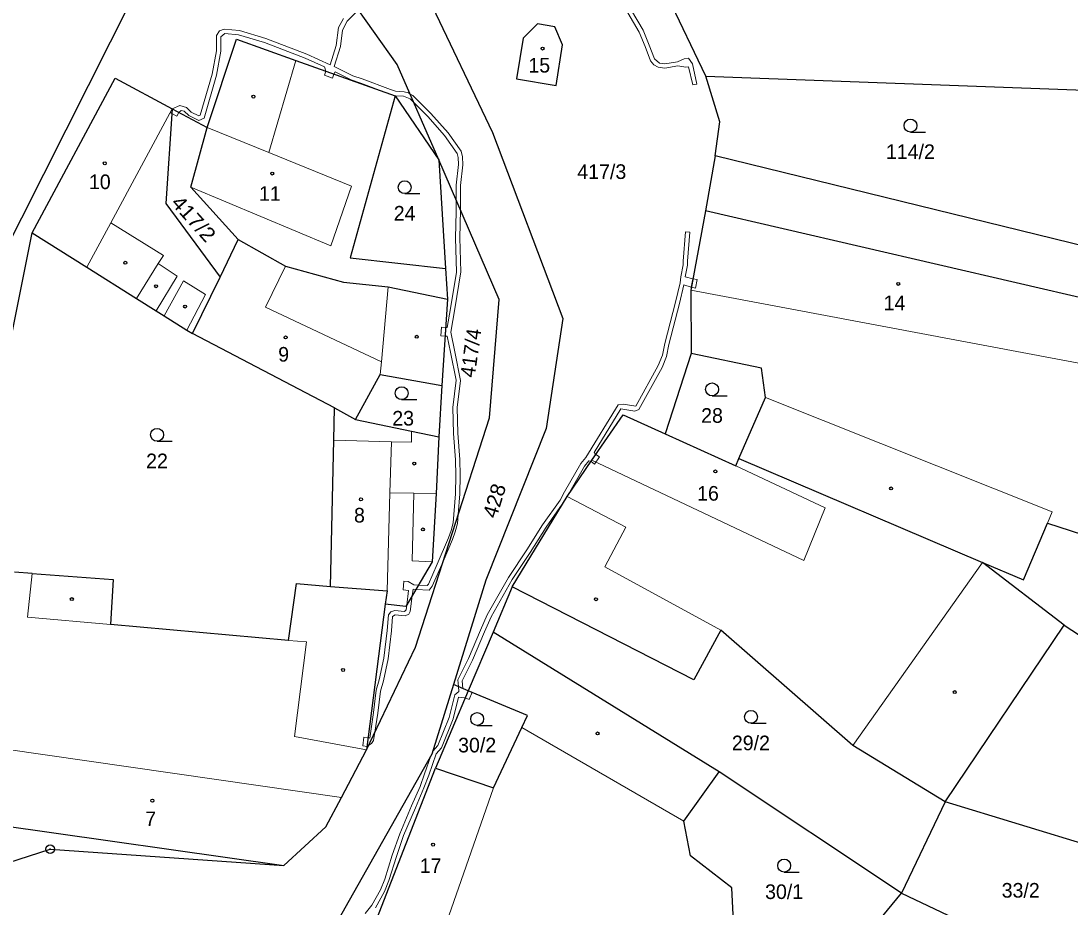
# Model space of a CAD drawing. Extents: x -791548 to -789311, y -1142631 to -1140855.
# Drawn here: x -790327.9 to -790206, y -1142218.6 to -1142115.7 of the extents above; entities that cross this region are included whole.
import ezdxf
from ezdxf.enums import TextEntityAlignment as Align

# ---------------------------------------------------------------- set-up
doc = ezdxf.new("R2010")
doc.units = 0
doc.header["$LTSCALE"] = 0.68
for name, color, linetype, lineweight in [('1', 7, 'Continuous', 25), ('13', 7, 'Continuous', 13), ('3', 7, 'Continuous', 25), ('4', 7, 'Continuous', 13), ('5', 7, 'Continuous', 25), ('8', 7, 'Continuous', 25)]:
    doc.layers.add(name, color=color, linetype=linetype, lineweight=lineweight)
doc.layers.add('2', color=7, linetype='Continuous')

msp = doc.modelspace()

# ---------------------------------------------------------------- linework, layer by layer
at = {"layer": '1'}
for p, q in [((-790284.19, -1142120.71), (-790294.25, -1142106.51)), ((-790248.33, -1142122.09), (-790253.96, -1142110.28)), ((-790330.46, -1142143.68), (-790314.29, -1142111.65)), ((-790280.51, -1142113.07), (-790273.1, -1142128.64)), ((-790267.88, -1142115.98), (-790269.54, -1142117.64)), ((-790265.88, -1142116.33), (-790267.88, -1142115.98)), ((-790264.98, -1142118.43), (-790265.88, -1142116.33)), ((-790306.29, -1142128.03), (-790302.86, -1142117.79)), ((-790302.86, -1142117.79), (-790295.98, -1142120.26)), ((-790265.7, -1142123.15), (-790264.98, -1142118.43)), ((-790295.98, -1142120.26), (-790284.42, -1142124.37)), ((-790279.36, -1142131.81), (-790284.19, -1142120.71)), ((-790326.62, -1142140.29), (-790316.96, -1142122.32)), ((-790316.96, -1142122.32), (-790310.35, -1142125.86)), ((-790248.33, -1142122.09), (-790202.6, -1142123.76)), ((-790246.69, -1142127.37), (-790248.33, -1142122.09)), ((-790284.42, -1142124.37), (-790289.66, -1142143.18)), ((-790284.42, -1142124.37), (-790279.36, -1142131.81)), ((-790310.35, -1142125.86), (-790311.1, -1142136.86)), ((-790310.35, -1142125.86), (-790306.29, -1142128.03)), ((-790247.24, -1142131.35), (-790246.69, -1142127.37)), ((-790308.18, -1142134.98), (-790306.29, -1142128.03)), ((-790273.1, -1142128.64), (-790264.92, -1142150.23)), ((-790272.32, -1142148.02), (-790279.36, -1142131.81)), ((-790279.36, -1142131.81), (-790278.58, -1142144.41)), ((-790247.24, -1142131.35), (-790248.37, -1142137.71)), ((-790203.93, -1142141.96), (-790247.24, -1142131.35)), ((-790302.66, -1142141.04), (-790308.18, -1142134.98)), ((-790311.1, -1142136.86), (-790304.75, -1142145.45)), ((-790248.37, -1142137.71), (-790250.07, -1142146.94)), ((-790202.22, -1142148.44), (-790248.37, -1142137.71)), ((-790329.14, -1142152.86), (-790326.62, -1142140.29)), ((-790326.62, -1142140.29), (-790320.27, -1142144.28)), ((-790304.75, -1142145.45), (-790302.66, -1142141.04)), ((-790302.66, -1142141.04), (-790297.19, -1142144.14)), ((-790289.66, -1142143.18), (-790278.58, -1142144.41)), ((-790320.27, -1142144.28), (-790314.51, -1142147.9)), ((-790297.19, -1142144.14), (-790290.44, -1142146.01)), ((-790278.58, -1142144.41), (-790278.35, -1142148.01)), ((-790307.99, -1142151.97), (-790304.75, -1142145.45)), ((-790290.44, -1142146.01), (-790285.25, -1142146.56)), ((-790285.25, -1142146.56), (-790278.35, -1142148.01)), ((-790250.07, -1142146.94), (-790250.03, -1142154.31)), ((-790314.51, -1142147.9), (-790312.21, -1142149.34)), ((-790278.35, -1142148.01), (-790278.99, -1142158.03)), ((-790273.47, -1142161.79), (-790272.32, -1142148.02)), ((-790312.21, -1142149.34), (-790311.29, -1142149.92)), ((-790311.29, -1142149.92), (-790308.65, -1142151.58)), ((-790264.92, -1142150.23), (-790266.89, -1142163.02)), ((-790308.65, -1142151.58), (-790307.99, -1142151.97)), ((-790291.47, -1142160.63), (-790307.99, -1142151.97)), ((-790250.03, -1142154.31), (-790253.04, -1142163.65)), ((-790241.85, -1142156.02), (-790250.03, -1142154.31)), ((-790241.38, -1142159.41), (-790241.85, -1142156.02)), ((-790289.04, -1142161.96), (-790286.17, -1142156.76)), ((-790286.17, -1142156.76), (-790278.99, -1142158.03)), ((-790278.99, -1142158.03), (-790279.37, -1142163.99)), ((-790244.48, -1142166.53), (-790241.38, -1142159.41)), ((-790291.55, -1142164.4), (-790291.47, -1142160.63)), ((-790291.47, -1142160.63), (-790289.04, -1142161.96)), ((-790261.55, -1142166.71), (-790257.93, -1142161.43)), ((-790257.93, -1142161.43), (-790253.04, -1142163.65)), ((-790289.04, -1142161.96), (-790282.51, -1142163.33)), ((-790282.08, -1142188.44), (-790273.47, -1142161.79)), ((-790282.51, -1142163.33), (-790279.37, -1142163.99)), ((-790279.37, -1142163.99), (-790279.68, -1142170.57)), ((-790266.89, -1142163.02), (-790273.87, -1142180.67)), ((-790253.04, -1142163.65), (-790244.85, -1142167.37)), ((-790291.96, -1142181.38), (-790291.55, -1142164.4)), ((-790264.45, -1142170.93), (-790261.55, -1142166.71)), ((-790244.85, -1142167.37), (-790244.48, -1142166.53)), ((-790244.48, -1142166.53), (-790216.16, -1142178.61)), ((-790279.68, -1142170.57), (-790280.12, -1142178.53)), ((-790270.84, -1142181.44), (-790264.45, -1142170.93)), ((-790211.41, -1142180.63), (-790208.6, -1142174.01)), ((-790208.6, -1142174.01), (-790196.56, -1142177.95)), ((-790280.12, -1142178.53), (-790283.17, -1142183.7)), ((-790206.67, -1142185.87), (-790216.16, -1142178.61)), ((-790216.16, -1142178.61), (-790211.41, -1142180.63)), ((-790326.63, -1142179.87), (-790328.69, -1142179.71)), ((-790326.63, -1142179.87), (-790317.2, -1142180.56)), ((-790317.2, -1142180.56), (-790317.53, -1142185.8)), ((-790296.82, -1142187.65), (-790295.91, -1142181.06)), ((-790295.91, -1142181.06), (-790291.96, -1142181.38)), ((-790273.87, -1142180.67), (-790277.65, -1142192.79)), ((-790291.96, -1142181.38), (-790285.36, -1142181.91)), ((-790285.36, -1142181.91), (-790285.6, -1142183.44)), ((-790270.84, -1142181.44), (-790273.05, -1142186.68)), ((-790249.71, -1142192.23), (-790270.84, -1142181.44)), ((-790285.6, -1142183.44), (-790287.75, -1142200.37)), ((-790283.17, -1142183.7), (-790285.6, -1142183.44)), ((-790296.82, -1142187.65), (-790317.53, -1142185.8)), ((-790220.5, -1142206.42), (-790206.67, -1142185.87)), ((-790206.67, -1142185.87), (-790191, -1142196.24)), ((-790273.05, -1142186.68), (-790275.93, -1142193.5)), ((-790246.77, -1142202.93), (-790273.05, -1142186.68)), ((-790246.58, -1142186.47), (-790249.71, -1142192.23)), ((-790231.23, -1142199.87), (-790246.58, -1142186.47)), ((-790287.75, -1142200.37), (-790282.08, -1142188.44)), ((-790277.65, -1142192.79), (-790280.17, -1142200.89)), ((-790275.93, -1142193.5), (-790277.65, -1142192.79)), ((-790275.93, -1142193.5), (-790279.72, -1142202.49)), ((-790269.06, -1142196.4), (-790275.93, -1142193.5)), ((-790269.71, -1142197.79), (-790269.06, -1142196.4)), ((-790273, -1142204.78), (-790269.71, -1142197.79)), ((-790290.68, -1142205.92), (-790287.75, -1142200.37)), ((-790220.5, -1142206.42), (-790231.23, -1142199.87)), ((-790280.17, -1142200.89), (-790291.64, -1142221.17)), ((-790286.57, -1142220), (-790279.72, -1142202.49)), ((-790279.72, -1142202.49), (-790273, -1142204.78)), ((-790250.88, -1142208.65), (-790246.77, -1142202.93)), ((-790225.57, -1142217.02), (-790246.77, -1142202.93)), ((-790292.47, -1142209.32), (-790290.68, -1142205.92)), ((-790220.5, -1142206.42), (-790225.57, -1142217.02)), ((-790197.2, -1142213.53), (-790220.5, -1142206.42)), ((-790331.39, -1142209), (-790297.38, -1142213.8)), ((-790250.11, -1142212.7), (-790250.88, -1142208.65)), ((-790297.38, -1142213.8), (-790292.47, -1142209.32)), ((-790336.95, -1142215.9), (-790324.53, -1142211.91)), ((-790324.53, -1142211.91), (-790297.38, -1142213.8)), ((-790245.28, -1142216.42), (-790250.11, -1142212.7)), ((-790245.13, -1142219.55), (-790245.28, -1142216.42)), ((-790234.29, -1142227.54), (-790225.57, -1142217.02)), ((-790225.57, -1142217.02), (-790202.5, -1142227.96))]:
    msp.add_line(p, q, dxfattribs=at)
msp.add_lwpolyline([(-790269.54, -1142117.64), (-790270.34, -1142122.38), (-790265.7, -1142123.15)], dxfattribs=at)
at = {"layer": '13'}
for points in [[(-790290.42, -1142115.39), (-790291, -1142116.4), (-790291.27, -1142118.52), (-790291.98, -1142120.76), (-790294.7, -1142119.52), (-790299.46, -1142117.7), (-790302.54, -1142116.77), (-790304.29, -1142116.62), (-790304.84, -1142116.79), (-790305.19, -1142117.35), (-790305.2, -1142119.12), (-790305.68, -1142121.85), (-790307.08, -1142126.61), (-790307.23, -1142126.68), (-790308.12, -1142126.24), (-790308.7, -1142125.72), (-790309.47, -1142125.5), (-790310.35, -1142125.86), (-790310.39, -1142126.41), (-790309.81, -1142126.72), (-790309.57, -1142126.28), (-790309.29, -1142126.07), (-790308.94, -1142126.16), (-790308.4, -1142126.66), (-790307.23, -1142127.24), (-790306.62, -1142126.94), (-790305.2, -1142121.97), (-790304.7, -1142119.16), (-790304.69, -1142117.49), (-790304.23, -1142117.12), (-790302.64, -1142117.27), (-790299.62, -1142118.18), (-790294.9, -1142119.98), (-790292.65, -1142121), (-790292.49, -1142121.5), (-790291.55, -1142121.83), (-790291.4, -1142121.57), (-790289.54, -1142122.49), (-790288.41, -1142122.88), (-790285.14, -1142124.11), (-790284.42, -1142124.37), (-790283.46, -1142124.38), (-790282.7, -1142124.71), (-790282.26, -1142125.15), (-790282.71, -1142124.11), (-790282.87, -1142124), (-790283.4, -1142123.88), (-790284.39, -1142123.82), (-790284.98, -1142123.63), (-790288.25, -1142122.4), (-790289.34, -1142122.03), (-790291.51, -1142120.95), (-790290.77, -1142118.62), (-790290.54, -1142116.74), (-790290.02, -1142115.69), (-790288.69, -1142114.36)], [(-790257.37, -1142114.73), (-790256.05, -1142116.95), (-790255.37, -1142118.64), (-790254.74, -1142120.31), (-790254.37, -1142120.76), (-790253.86, -1142121.03), (-790253.09, -1142121.13), (-790251.56, -1142120.89), (-790250.66, -1142121.04), (-790250.32, -1142120.99), (-790249.84, -1142123.1), (-790249.35, -1142122.99), (-790249.88, -1142120.63), (-790250.33, -1142119.98), (-790250.82, -1142120.06), (-790251.62, -1142120.39), (-790253.09, -1142120.63), (-790253.7, -1142120.55), (-790254.3, -1142120.05), (-790254.91, -1142118.46), (-790255.61, -1142116.73), (-790256.95, -1142114.45)], [(-790250.68, -1142140.15), (-790250.95, -1142143.56), (-790250.96, -1142144), (-790251.22, -1142145.39), (-790251.32, -1142146.09), (-790251.85, -1142148.36), (-790253.1, -1142153.15), (-790253.36, -1142154.52), (-790253.84, -1142155.7), (-790256.45, -1142160.42), (-790257.91, -1142160.2), (-790258.49, -1142160.27), (-790262.25, -1142166.4), (-790262.85, -1142167.11), (-790264.74, -1142170.38), (-790265.26, -1142171.34), (-790267.29, -1142174.23), (-790269.14, -1142177.14), (-790271.26, -1142180.33), (-790273.72, -1142184.69), (-790274.52, -1142186.46), (-790275.89, -1142189.75), (-790277.13, -1142192.24), (-790277.08, -1142193.03), (-790277.04, -1142193.58), (-790277.51, -1142193.97), (-790278.17, -1142196.62), (-790279.47, -1142199.88), (-790280.06, -1142200.52), (-790280.17, -1142200.89), (-790280.28, -1142201.09), (-790281.01, -1142203.15), (-790281.54, -1142204.62), (-790282.51, -1142206.9), (-790283.9, -1142210.14), (-790284.77, -1142212.62), (-790285.64, -1142215.42), (-790286.13, -1142216.63), (-790287.15, -1142218.44), (-790287.91, -1142219.39)], [(-790265, -1142171.83), (-790264.45, -1142170.93), (-790262.43, -1142167.39), (-790261.93, -1142166.8), (-790261.66, -1142166.88), (-790261.55, -1142166.71), (-790261.1, -1142166.05), (-790261.3, -1142165.82), (-790258.19, -1142160.73), (-790256.56, -1142161.01), (-790256.09, -1142160.82), (-790253.38, -1142155.92), (-790252.88, -1142154.66), (-790252.62, -1142153.25), (-790251.37, -1142148.48), (-790250.86, -1142146.34), (-790250.01, -1142146.61), (-790249.83, -1142145.62), (-790250.71, -1142145.41), (-790250.46, -1142144.06), (-790250.45, -1142143.58), (-790250.18, -1142140.19), (-790250.68, -1142140.15)], [(-790286.73, -1142218.72), (-790285.67, -1142216.85), (-790285.16, -1142215.58), (-790284.29, -1142212.78), (-790283.44, -1142210.32), (-790282.05, -1142207.1), (-790281.08, -1142204.8), (-790280.53, -1142203.31), (-790279.66, -1142200.83), (-790279.03, -1142200.16), (-790277.69, -1142196.78), (-790277.07, -1142194.25), (-790276.28, -1142194.33), (-790275.93, -1142193.5), (-790276.56, -1142193.24), (-790276.63, -1142192.34), (-790275.43, -1142189.95), (-790274.06, -1142186.66), (-790273.28, -1142184.91), (-790270.84, -1142180.59), (-790268.72, -1142177.42), (-790266.87, -1142174.51), (-790265, -1142171.83)]]:
    msp.add_lwpolyline(points, dxfattribs=at)
for points in [[(-790291.55, -1142121.83), (-790292.49, -1142121.5), (-790292.66, -1142121.97), (-790291.72, -1142122.31)], [(-790282.71, -1142124.11), (-790282.26, -1142125.15), (-790280.64, -1142126.77), (-790278.68, -1142128.97), (-790277.21, -1142131.06), (-790277.11, -1142131.51), (-790277.05, -1142132.36), (-790277.34, -1142134.76), (-790277.33, -1142136.47), (-790276.82, -1142137.66), (-790276.84, -1142134.78), (-790276.55, -1142132.38), (-790276.61, -1142131.45), (-790276.75, -1142130.78), (-790278.28, -1142128.65), (-790280.28, -1142126.43), (-790282.38, -1142124.33)], [(-790310.39, -1142126.41), (-790310.35, -1142125.86), (-790310.59, -1142126.3)], [(-790277.33, -1142136.47), (-790277.33, -1142137.86), (-790277.42, -1142140.88), (-790277.31, -1142144.85), (-790278.01, -1142149.06), (-790278.38, -1142151.29), (-790278.56, -1142151.28), (-790278.62, -1142152.28), (-790278.38, -1142152.29), (-790278, -1142154.16), (-790277.32, -1142157.39), (-790277.71, -1142160.57), (-790277.65, -1142163.6), (-790277.4, -1142166.65), (-790277.36, -1142168.47), (-790277.43, -1142170.6), (-790277.68, -1142173.99), (-790277.92, -1142174.89), (-790278.22, -1142175.75), (-790279.54, -1142178.78), (-790280.55, -1142181.1), (-790280.71, -1142181.28), (-790281.71, -1142181.23), (-790282, -1142181.72), (-790280.49, -1142181.8), (-790280.13, -1142181.36), (-790278.86, -1142178.48), (-790277.11, -1142173.04), (-790276.93, -1142170.62), (-790276.86, -1142168.47), (-790276.9, -1142166.63), (-790277.15, -1142163.58), (-790277.21, -1142160.59), (-790276.82, -1142157.43), (-790277.5, -1142154.12), (-790277.97, -1142151.82), (-790277.51, -1142149.1), (-790276.81, -1142144.83), (-790276.92, -1142140.88), (-790276.82, -1142137.66)], [(-790249.34, -1142145.71), (-790249.83, -1142145.62), (-790250.01, -1142146.61), (-790249.52, -1142146.7)], [(-790279.06, -1142151.25), (-790279.12, -1142152.25), (-790278.62, -1142152.28), (-790278.56, -1142151.28)], [(-790261.1, -1142166.05), (-790261.55, -1142166.71), (-790261.66, -1142166.88), (-790261.25, -1142167.16), (-790260.69, -1142166.33)], [(-790277.11, -1142173.04), (-790278.86, -1142178.48), (-790277.76, -1142175.93), (-790277.44, -1142175.03), (-790277.18, -1142174.07)], [(-790281.71, -1142181.23), (-790282.25, -1142181.2), (-790282.92, -1142180.82), (-790283.41, -1142180.78), (-790283.5, -1142181.77), (-790282.88, -1142181.86), (-790283.08, -1142183.55), (-790282.45, -1142182.47), (-790282.35, -1142181.7), (-790282, -1142181.72)], [(-790283.08, -1142183.55), (-790283.15, -1142184.12), (-790283.36, -1142184.29), (-790284.48, -1142184.19), (-790284.92, -1142184.33), (-790285.22, -1142184.68), (-790285.36, -1142186.5), (-790285.74, -1142189.73), (-790286.27, -1142192.23), (-790286.64, -1142193.45), (-790286.93, -1142196.04), (-790287.39, -1142199.01), (-790287.57, -1142198.99), (-790287.7, -1142199.98), (-790287.51, -1142199.86), (-790286.78, -1142198.33), (-790286.43, -1142196.1), (-790286.14, -1142193.55), (-790285.79, -1142192.35), (-790285.24, -1142189.81), (-790284.86, -1142186.54), (-790284.74, -1142184.88), (-790284.42, -1142184.69), (-790283.26, -1142184.81), (-790282.84, -1142184.59), (-790282.67, -1142184.28), (-790282.45, -1142182.47)], [(-790275.82, -1142194.52), (-790275.47, -1142193.69), (-790275.93, -1142193.5), (-790276.28, -1142194.33)], [(-790287.7, -1142199.98), (-790287.57, -1142198.99), (-790288.07, -1142198.92), (-790288.2, -1142199.91)], [(-790286.78, -1142198.33), (-790287.51, -1142199.86), (-790287.17, -1142199.64), (-790286.93, -1142199.28)]]:
    msp.add_lwpolyline(points, close=True, dxfattribs=at)
at = {"layer": '3'}
for p, q in [((-790224.533, -1142128.57), (-790222.783, -1142128.57)), ((-790283.323, -1142135.73), (-790281.573, -1142135.73)), ((-790283.673, -1142159.67), (-790281.923, -1142159.67)), ((-790247.593, -1142159.23), (-790245.843, -1142159.23)), ((-790312.103, -1142164.51), (-790310.353, -1142164.51)), ((-790274.893, -1142197.54), (-790273.143, -1142197.54)), ((-790243.073, -1142197.29), (-790241.323, -1142197.29)), ((-790239.213, -1142214.58), (-790237.463, -1142214.58))]:
    msp.add_line(p, q, dxfattribs=at)
for centre in [(-790224.5329, -1142127.8198), (-790283.3229, -1142134.9798), (-790247.5929, -1142158.4798), (-790283.6729, -1142158.9198), (-790312.1029, -1142163.7598), (-790274.8929, -1142196.7898), (-790243.0729, -1142196.5398), (-790239.2129, -1142213.8298)]:
    msp.add_circle(centre, 0.75, dxfattribs=at)
at = {"layer": '4'}
for p, q in [((-790310.35, -1142125.86), (-790317.48, -1142139.11)), ((-790289.5, -1142134.84), (-790299.1, -1142130.95)), ((-790308.18, -1142134.98), (-790291.9, -1142141.8)), ((-790291.9, -1142141.8), (-790289.5, -1142134.84)), ((-790317.48, -1142139.11), (-790320.27, -1142144.28)), ((-790311.37, -1142142.9), (-790317.48, -1142139.11)), ((-790311.97, -1142143.86), (-790311.37, -1142142.9)), ((-790314.51, -1142147.9), (-790311.97, -1142143.86)), ((-790309.77, -1142145.31), (-790311.97, -1142143.86)), ((-790297.19, -1142144.14), (-790299.5, -1142148.91)), ((-790312.21, -1142149.34), (-790309.77, -1142145.31)), ((-790309.02, -1142145.87), (-790311.29, -1142149.92)), ((-790306.46, -1142147.46), (-790309.02, -1142145.87)), ((-790286.02, -1142155.27), (-790285.25, -1142146.56)), ((-790250.07, -1142146.94), (-790203.71, -1142155.65)), ((-790308.65, -1142151.58), (-790306.46, -1142147.46)), ((-790299.5, -1142148.91), (-790286.02, -1142155.27)), ((-790286.02, -1142155.27), (-790286.17, -1142156.76)), ((-790208.08, -1142172.7), (-790241.38, -1142159.41)), ((-790282.52, -1142164.63), (-790282.51, -1142163.33)), ((-790284.86, -1142164.57), (-790291.55, -1142164.4)), ((-790285.03, -1142170.51), (-790284.86, -1142164.57)), ((-790284.86, -1142164.57), (-790282.52, -1142164.63)), ((-790236.94, -1142178.36), (-790261.55, -1142166.71)), ((-790244.85, -1142167.37), (-790234.44, -1142172.26)), ((-790285.36, -1142181.91), (-790285.03, -1142170.51)), ((-790285.03, -1142170.51), (-790282.24, -1142170.54)), ((-790282.45, -1142178.4), (-790282.24, -1142170.54)), ((-790282.24, -1142170.54), (-790279.68, -1142170.57)), ((-790264.45, -1142170.93), (-790257.62, -1142174.48)), ((-790234.44, -1142172.26), (-790236.94, -1142178.36)), ((-790208.6, -1142174.01), (-790208.08, -1142172.7)), ((-790257.62, -1142174.48), (-790260.07, -1142179.1)), ((-790280.12, -1142178.53), (-790282.45, -1142178.4)), ((-790231.23, -1142199.87), (-790216.16, -1142178.61)), ((-790326.63, -1142179.87), (-790327.15, -1142184.94)), ((-790260.07, -1142179.1), (-790246.58, -1142186.47)), ((-790327.15, -1142184.94), (-790317.53, -1142185.8)), ((-790294.75, -1142187.83), (-790296.82, -1142187.65)), ((-790294.75, -1142187.83), (-790296.14, -1142198.81)), ((-790250.88, -1142208.65), (-790269.71, -1142197.79)), ((-790287.75, -1142200.37), (-790296.14, -1142198.81)), ((-790329.97, -1142200.24), (-790290.68, -1142205.92)), ((-790279.2, -1142222.5), (-790273, -1142204.78))]:
    msp.add_line(p, q, dxfattribs=at)
msp.add_lwpolyline([(-790295.98, -1142120.26), (-790299.1, -1142130.95), (-790306.29, -1142128.03)], dxfattribs=at)
at = {"layer": '5'}
for centre in [(-790267.2988, -1142118.8633), (-790300.8988, -1142124.4533), (-790318.1788, -1142132.2033), (-790298.7188, -1142133.3933), (-790315.7968, -1142143.7592), (-790312.2188, -1142146.4833), (-790225.9588, -1142146.2133), (-790308.8388, -1142148.8533), (-790297.1588, -1142152.4433), (-790281.9188, -1142152.3633), (-790282.2088, -1142167.1033), (-790247.2088, -1142168.0133), (-790226.7788, -1142169.9933), (-790288.3988, -1142171.2633), (-790281.2088, -1142174.7633), (-790322.0088, -1142182.8533), (-790261.0888, -1142182.8733), (-790290.4788, -1142191.0933), (-790219.3788, -1142193.6633), (-790260.9088, -1142198.4733), (-790312.6488, -1142206.2833), (-790280.0188, -1142211.3933)]:
    msp.add_circle(centre, 0.175, dxfattribs=at)
at = {"layer": '8'}
for radius in [0.5, 0.0303]:
    msp.add_circle((-790324.5299, -1142211.91), radius, dxfattribs=at)

# ---------------------------------------------------------------- texts
at = {"layer": '2'}
for s, p in [('15', (-790267.679, -1142121.652)), ('114/2', (-790224.54, -1142131.702)), ('417/3', (-790260.41, -1142134.022)), ('10', (-790318.759, -1142135.202)), ('11', (-790298.989, -1142136.562)), ('24', (-790283.329, -1142138.862)), ('14', (-790226.389, -1142149.272)), ('9', (-790297.39, -1142155.252)), ('23', (-790283.499, -1142162.682)), ('28', (-790247.599, -1142162.362)), ('22', (-790312.109, -1142167.642)), ('16', (-790248.069, -1142171.412)), ('8', (-790288.58, -1142173.952)), ('30/2', (-790274.899, -1142200.672)), ('29/2', (-790243.079, -1142200.422)), ('7', (-790312.85, -1142209.242)), ('17', (-790280.309, -1142214.692)), ('30/1', (-790239.219, -1142217.712)), ('33/2', (-790211.719, -1142217.552))]:
    msp.add_text(s, height=1.7, dxfattribs=at).set_placement(p, align=Align.CENTER)
for s, rotation, width, p in [('417/2', 312, 1.1, (-790308.4815, -1142139.2072)), ('428', 73, 1.05, (-790272.0846, -1142171.6685))]:
    msp.add_text(s, height=1.7, rotation=rotation, dxfattribs=dict(at, width=width)).set_placement(p, align=Align.CENTER)
msp.add_text('417/4', height=1.7, rotation=82, dxfattribs=at).set_placement((-790274.7908, -1142154.3583), align=Align.CENTER)

doc.saveas('drawing.dxf')
